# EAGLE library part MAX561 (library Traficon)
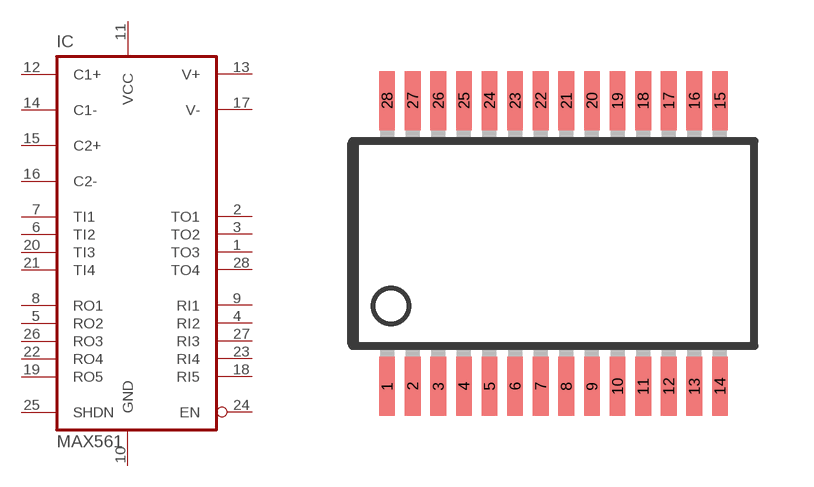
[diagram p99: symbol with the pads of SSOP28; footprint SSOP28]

Designator prefix IC

## MAX561CAI  [SSOP28]
1  TO3
2  TO1
3  TO2
4  RI2
5  RO2
6  TI2
7  TI1
8  RO1
9  RI1
10  GND
11  VCC
12  C1+
13  V+
14  C1-
15  C2+
16  C2-
17  V-
18  RI5
19  RO5
20  TI3
21  TI4
22  RO4
23  RI4
24  EN
25  SHDN
26  RO3
27  RI3
28  TO4

## Footprint SSOP28 (pad centres in mm)
Shrink Small Outline Package package type SS
smd 0.4 x 1.5: 1 -4.225,-3.625; 2 -3.575,-3.625; 3 -2.925,-3.625; 4 -2.275,-3.625; 5 -1.625,-3.625; 6 -0.975,-3.625; 7 -0.325,-3.625; 8 0.325,-3.625; 9 0.975,-3.625; 10 1.625,-3.625; 11 2.275,-3.625; 12 2.925,-3.625; 13 3.575,-3.625; 14 4.225,-3.625; 15 4.225,3.625; 16 3.575,3.625; 17 2.925,3.625; 18 2.275,3.625; 19 1.625,3.625; 20 0.975,3.625; 21 0.325,3.625; 22 -0.325,3.625; 23 -0.975,3.625; 24 -1.625,3.625; 25 -2.275,3.625; 26 -2.925,3.625; 27 -3.575,3.625; 28 -4.225,3.625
